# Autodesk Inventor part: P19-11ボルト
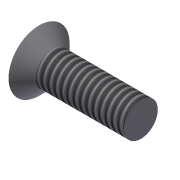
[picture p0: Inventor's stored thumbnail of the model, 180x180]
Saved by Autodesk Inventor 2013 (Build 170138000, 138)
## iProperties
Shininess: 64.0
Length Units: 11269
Angle Units: 11279
Time Units: 11290
Mass Units: 11284
Length Display Precision: 2
Angle Display Precision: 1
Created: 2002-10
Part Number: P19-11ボルト
Document SubType Name: ﾓﾃﾞﾘﾝｸﾞ
Designer: 株式会社富士システム
Stock Number: P19-11ボルト
Density: 1 g/cm^3
Material: 一般
Density: 0.0
Volumn: 0.0
Area: 0.0
PropertySet Name: Model Information
Control State: 0
Master: False
Checked Out: False
Author: 株式会社富士システム
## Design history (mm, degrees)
sketch "ｽｹｯﾁ1"
  geometry: L1 (0, 0)-(0, -6); L2 (0, -6)-(2.677, -3.324); L3 (2.677, -3.324)-(20, -3.323); L4 (20, -3.323)-(20, 0); L5 (20, 0)-(0, 0); 1 further point
  constraints: 10 end point, 2 perpendicular, 1 coincident, 1 parallel, 1 vertical
  dimensions: "d14" = 45 deg angle of L5 L2; "d15" = 12 diameter of L1.end L5; "d16" = 20 distance between parallel lines of L4 L1; "d17" = 6.647 diameter of L3 L5
revolve "回転1" sketch "ｽｹｯﾁ1" stored, may be unused: angle "d5" = 90 deg
feature "ねじ1" dims "d6" = 10, "d7" = 0
sketch "ｽｹｯﾁ2"
  geometry: L1 (0, -6)-(0, 6); L2 (-6, 0)-(6, 0); L3 (-5.999, 0.718)-(-5.957, 0.718); L4 (-5.999, -0.718)-(-5.957, -0.718); L5 (5.957, -0.718)-(5.999, -0.718); L6 (5.957, 0.718)-(5.999, 0.718); L7 (0.718, -5.999)-(0.718, -5.957); L8 (-0.718, -5.999)-(-0.718, -5.957); L9 (-0.7, -3.938)-(-0.7, -0.7); L10 (0.7, -3.938)-(0.7, -0.7); L11 (0.7, 0.7)-(0.7, 3.938); L12 (0.718, 5.957)-(0.718, 5.999); L13 (-0.7, 0.7)-(-0.7, 3.938); L14 (-0.718, 5.957)-(-0.718, 5.999); L15 (-3.938, 0.7)-(-0.7, 0.7); L16 (0.7, 0.7)-(3.938, 0.7); L17 (-3.938, -0.7)-(-0.7, -0.7); L18 (0.7, -0.7)-(3.938, -0.7); A1 r 4 centre (0, 0) between (0.7, 3.938) and (-0.7, 3.938); A2 r 4 centre (0, 0) between (3.938, -0.7) and (3.938, 0.7); A3 r 4 centre (0, 0) between (-3.938, 0.7) and (-3.938, -0.7); A4 r 4 centre (0, 0) between (-0.7, -3.938) and (0.7, -3.938); 1 further point
  constraints: 36 end point, 8 point on circle, 4 centre point, 2 midpoint, 1 coincident, 1 perpendicular, 1 vertical, 13 other
extrude "押し出し1" cut sketch "ｽｹｯﾁ2" distance "d12" = 1; taper "d13" = 0 deg
node "ソリッド1"
node "ソリッド ボディ"
node "サーフェス ボディ"
other parameters: "d8" = 0.7, "d9" = 0.7 (= d8), "d10" = 0.7 (= d8), "d11" = 0.7 (= d8)
